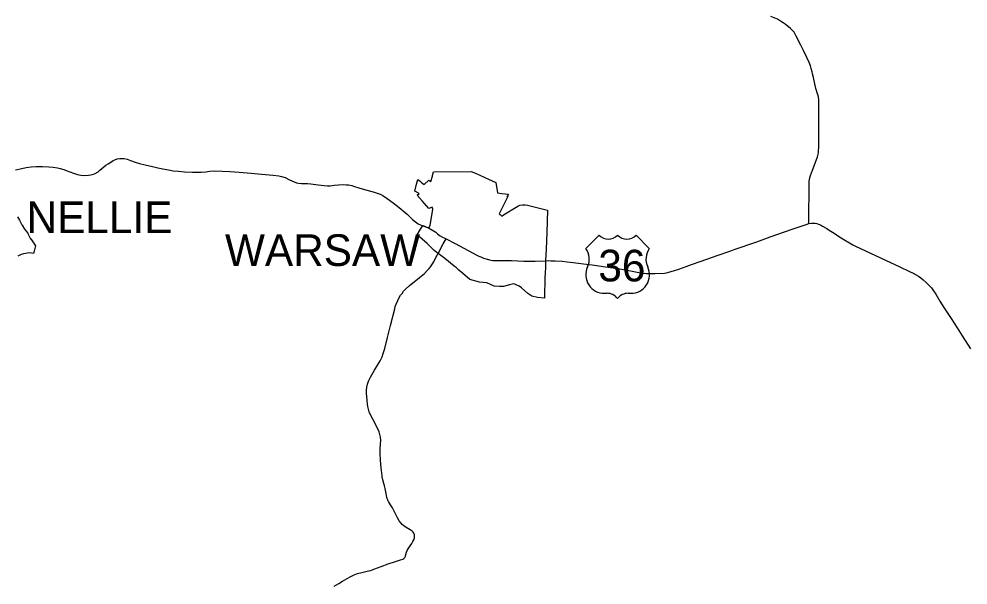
# Model space of a CAD drawing. Extents: x 2004415 to 2276415, y 751181 to 927181.
# Drawn here: x 2090901 to 2124487, y 838735 to 858783 of the extents above; entities that cross this region are included whole.
import ezdxf

# ---------------------------------------------------------------- set-up
doc = ezdxf.new("R2010")
doc.units = 0
for name, color, linetype in [('GM_X_Corporation', 7, 'Continuous'), ('GM_X_Corporation_Text', 7, 'Continuous'), ('GM_X_State_Route', 7, 'Continuous'), ('GM_X_US_Location', 7, 'Continuous'), ('GM_X_US_Route', 7, 'Continuous'), ('GM_X_US_Shield', 7, 'Continuous')]:
    doc.layers.add(name, color=color, linetype=linetype)

msp = doc.modelspace()

# ---------------------------------------------------------------- linework, layer by layer
at = {"layer": 'GM_X_Corporation'}
msp.add_lwpolyline([(2105113, 851335), (2105179, 851439), (2105179, 851439), (2105195, 851464), (2105195, 851464), (2105207, 851460), (2105227, 851454), (2105278, 851437), (2105334, 851414), (2105405, 851380), (2105455, 851471), (2105553, 852041), (2105519, 852116), (2105408, 852074), (2105248, 852242), (2105166, 852339), (2104993, 852542), (2105064, 852604), (2104911, 852690), (2104974, 852932), (2105015, 853092), (2105104, 853034), (2105152, 852992), (2105197, 852952), (2105199, 852950), (2105240, 852922), (2105404, 853072), (2105478, 853021), (2105531, 853219), (2105537, 853242), (2105572, 853370), (2106903, 853376), (2107057, 853326), (2107514, 853106), (2107775, 852990), (2107833, 852624), (2107987, 852607), (2108228, 852582), (2108167, 852483), (2108163, 852478), (2108188, 852485), (2108199, 852488), (2108206, 852491), (2107893, 851878), (2107901, 851874), (2107911, 851868), (2107920, 851861), (2107930, 851855), (2107939, 851848), (2107947, 851841), (2107956, 851834), (2107959, 851831), (2107964, 851826), (2107972, 851818), (2107980, 851810), (2107988, 851802), (2108054, 851844), (2108551, 852157), (2108632, 852189), (2108724, 852199), (2108819, 852196), (2108892, 852185), (2109602, 852017), (2109586, 851225), (2109558, 850625), (2109539, 850224), (2109530, 849966), (2109525, 849809), (2109515, 849607), (2109512, 849509), (2109501, 849036), (2109497, 848891), (2109257, 848922), (2109048, 848971), (2108983, 849013), (2108908, 849065), (2108681, 849258), (2108598, 849315), (2108540, 849349), (2108468, 849383), (2108407, 849398), (2108265, 849366), (2108054, 849310), (2107903, 849304), (2107715, 849322), (2107457, 849441), (2107193, 849460), (2106852, 849561), (2106597, 849775), (2106470, 849892), (2106369, 849976), (2106304, 850030), (2105967, 850303), (2105591, 850579), (2105346, 850835), (2104989, 851139)], close=True, dxfattribs=at)
msp.add_lwpolyline([(2090850, 851775), (2090914, 851654), (2091007, 851492), (2091012, 851484), (2091102, 851343), (2091210, 851198), (2091217, 851189), (2091313, 850998), (2091317, 850993), (2091489, 850744), (2091439, 850561), (2091431, 850531), (2091424, 850506), (2091416, 850477), (2091272, 850498), (2091200, 850490), (2091060, 850462), (2090973, 850436), (2090857, 850378)], dxfattribs=at)
at = {"layer": 'GM_X_State_Route'}
for p, q in [((2106014, 850995), (2106333, 850828)), ((2106333, 850828), (2106648, 850663)), ((2106648, 850663), (2106956, 850500)), ((2113103, 849770), (2113160, 849770))]:
    msp.add_line(p, q, dxfattribs=at)
for points in [[(2119159, 853904), (2119172, 853945), (2119183, 853994), (2119193, 854042), (2119200, 854129), (2119205, 854223), (2119208, 854361), (2119203, 854853), (2119202, 855057), (2119205, 855744), (2119203, 855928), (2119195, 856016), (2119185, 856068), (2119150, 856170), (2119121, 856253), (2119103, 856322), (2119018, 856708), (2118987, 856839), (2118971, 856905), (2118939, 857033), (2118917, 857119), (2118869, 857237), (2118784, 857422), (2118666, 857664), (2118641, 857712), (2118568, 857853), (2118406, 858175), (2118359, 858268), (2118331, 858313), (2118298, 858356), (2118208, 858440), (2118017, 858595), (2117946, 858649), (2117856, 858709), (2117739, 858771), (2117511, 858875)], [(2118849, 851535), (2118852, 851622), (2118850, 851891), (2118853, 851941), (2118859, 852212), (2118860, 852359), (2118862, 852648), (2118863, 852966), (2118867, 853043), (2118876, 853096), (2118888, 853152), (2118915, 853235), (2118982, 853425), (2119146, 853864), (2119159, 853904)], [(2116213, 850615), (2117014, 850894), (2117489, 851063), (2118268, 851336), (2118578, 851442), (2118759, 851506), (2118849, 851535)], [(2105858, 850711), (2105916, 850820), (2106014, 850995)], [(2103942, 847505), (2104051, 847924), (2104197, 848516), (2104220, 848605), (2104249, 848688), (2104303, 848818), (2104351, 848913), (2104406, 848998), (2104457, 849066), (2104510, 849137), (2104571, 849205), (2104705, 849329), (2105077, 849631), (2105251, 849774), (2105348, 849871), (2105416, 849946), (2105475, 850020), (2105513, 850077), (2105578, 850181), (2105632, 850285), (2105700, 850412), (2105793, 850588), (2105858, 850711)], [(2106956, 850500), (2107109, 850420), (2107174, 850383), (2107241, 850356)], [(2113160, 849770), (2113410, 849767), (2113747, 849782), (2113820, 849791), (2113904, 849810), (2114096, 849871), (2114250, 849925), (2114509, 850016), (2114707, 850086), (2115048, 850204), (2115610, 850401), (2116098, 850574), (2116213, 850615)], [(2107241, 850356), (2107340, 850317), (2107439, 850284)], [(2107439, 850284), (2107558, 850253), (2107676, 850234), (2107790, 850225), (2107947, 850225), (2108145, 850228), (2108329, 850223), (2108558, 850212), (2108771, 850203), (2108923, 850200), (2109174, 850206), (2109535, 850219), (2109624, 850223), (2109719, 850219)], [(2109719, 850219), (2109878, 850214), (2110125, 850203), (2110303, 850184), (2110518, 850156), (2110697, 850135), (2110884, 850109)], [(2110884, 850109), (2111184, 850070), (2111653, 850008), (2112009, 849955), (2112361, 849893), (2112599, 849847), (2112778, 849812), (2112950, 849782), (2113021, 849775), (2113103, 849770)], [(2104582, 839756), (2104595, 839814), (2104618, 839899), (2104644, 839959), (2104674, 840012), (2104747, 840125), (2104805, 840212), (2104845, 840277), (2104874, 840335), (2104895, 840404), (2104903, 840467), (2104899, 840512), (2104880, 840574), (2104856, 840610), (2104814, 840648), (2104742, 840693), (2104602, 840775), (2104519, 840833), (2104461, 840884), (2104410, 840939), (2104358, 841009), (2104301, 841116), (2104173, 841380), (2104121, 841472), (2104054, 841575), (2103981, 841688), (2103952, 841742), (2103924, 841830), (2103898, 841975), (2103863, 842155), (2103833, 842254), (2103811, 842329), (2103773, 842466), (2103757, 842565), (2103750, 842603), (2103723, 842887), (2103698, 843156), (2103680, 843390), (2103680, 843566), (2103693, 843728), (2103703, 843866), (2103699, 843967), (2103677, 844067), (2103646, 844155), (2103587, 844288), (2103424, 844604), (2103364, 844718), (2103294, 844875), (2103267, 844961), (2103245, 845059), (2103235, 845136), (2103223, 845278), (2103199, 845530), (2103197, 845635), (2103210, 845741), (2103237, 845851), (2103273, 845955), (2103340, 846094), (2103485, 846349), (2103680, 846672), (2103749, 846818), (2103791, 846934), (2103815, 847001), (2103847, 847109), (2103942, 847505)], [(2102051, 838694), (2102215, 838785), (2102349, 838868), (2102513, 838966), (2102648, 839042), (2102768, 839099), (2102882, 839140), (2103031, 839179), (2103269, 839235), (2103354, 839254), (2103462, 839292), (2103717, 839394), (2103963, 839486), (2104221, 839572), (2104407, 839625), (2104480, 839651), (2104525, 839678), (2104556, 839711), (2104582, 839756)]]:
    msp.add_lwpolyline(points, dxfattribs=at)
at = {"layer": 'GM_X_US_Route'}
for p, q in [((2105846, 851083), (2106014, 850995)), ((2106014, 850995), (2106333, 850828)), ((2106333, 850828), (2106648, 850663)), ((2106648, 850663), (2106956, 850500)), ((2113103, 849770), (2113160, 849770))]:
    msp.add_line(p, q, dxfattribs=at)
for points in [[(2090777, 853440), (2090999, 853488), (2091159, 853519), (2091336, 853543), (2091506, 853558), (2091737, 853559), (2091959, 853549), (2092113, 853539), (2092264, 853516), (2092357, 853492), (2092489, 853450), (2092568, 853422), (2092825, 853319), (2092969, 853273), (2093095, 853249), (2093224, 853241), (2093358, 853249), (2093449, 853263), (2093539, 853285), (2093598, 853309), (2093701, 853371), (2093764, 853426), (2093905, 853549), (2093980, 853606), (2094054, 853655), (2094151, 853717), (2094240, 853767), (2094299, 853797), (2094379, 853827), (2094468, 853842), (2094533, 853847), (2094618, 853838), (2094735, 853814), (2094850, 853773), (2095008, 853712), (2095161, 853668), (2095368, 853617), (2095622, 853555), (2095820, 853511), (2095995, 853474), (2096195, 853434), (2096363, 853408), (2096540, 853391), (2096758, 853373), (2097040, 853359), (2097191, 853352), (2097350, 853355), (2097510, 853373), (2097661, 853390), (2097813, 853399), (2098097, 853396), (2098365, 853385), (2098690, 853361), (2099119, 853324), (2099483, 853291), (2099893, 853250), (2100098, 853227), (2100196, 853207), (2100324, 853163), (2100475, 853091), (2100635, 853016), (2100724, 852985), (2100792, 852968), (2100898, 852956), (2101117, 852955), (2101232, 852943), (2101495, 852909), (2101705, 852885), (2101815, 852877), (2101918, 852878), (2102058, 852894), (2102205, 852909), (2102381, 852917), (2102476, 852914), (2102562, 852907), (2102678, 852882), (2102775, 852854), (2102931, 852806), (2103216, 852724), (2103435, 852662), (2103577, 852619), (2103681, 852575), (2103772, 852530), (2103926, 852430), (2104148, 852273), (2104356, 852110), (2104634, 851864), (2104826, 851684), (2104933, 851594), (2105026, 851531), (2105133, 851481)], [(2105133, 851481), (2105324, 851414), (2105385, 851388), (2105449, 851351), (2105590, 851269), (2105654, 851230), (2105694, 851198), (2105718, 851178), (2105787, 851120), (2105834, 851089), (2105846, 851083)], [(2116213, 850615), (2117014, 850894), (2117489, 851063), (2118268, 851336), (2118578, 851442), (2118759, 851506), (2118849, 851535)], [(2118849, 851535), (2118953, 851552), (2119016, 851554), (2119076, 851548), (2119132, 851535), (2119195, 851516), (2119263, 851488), (2119343, 851443), (2119488, 851358), (2119571, 851306), (2119746, 851196), (2119905, 851094), (2120097, 850971), (2120288, 850851), (2120406, 850782), (2120502, 850732), (2121561, 850239), (2122077, 850000), (2122414, 849845)], [(2106956, 850500), (2107109, 850420), (2107174, 850383), (2107241, 850356)], [(2113160, 849770), (2113410, 849767), (2113747, 849782), (2113820, 849791), (2113904, 849810), (2114096, 849871), (2114250, 849925), (2114509, 850016), (2114707, 850086), (2115048, 850204), (2115610, 850401), (2116098, 850574), (2116213, 850615)], [(2107241, 850356), (2107340, 850317), (2107439, 850284)], [(2107439, 850284), (2107558, 850253), (2107676, 850234), (2107790, 850225), (2107947, 850225), (2108145, 850228), (2108329, 850223), (2108558, 850212), (2108771, 850203), (2108923, 850200), (2109174, 850206), (2109535, 850219), (2109624, 850223), (2109719, 850219)], [(2109719, 850219), (2109878, 850214), (2110125, 850203), (2110303, 850184), (2110518, 850156), (2110697, 850135), (2110884, 850109)], [(2110884, 850109), (2111184, 850070), (2111653, 850008), (2112009, 849955), (2112361, 849893), (2112599, 849847), (2112778, 849812), (2112950, 849782), (2113021, 849775), (2113103, 849770)], [(2122414, 849845), (2122418, 849843), (2122546, 849782), (2122647, 849727), (2122732, 849674), (2122819, 849616), (2122903, 849549), (2123009, 849455), (2123116, 849343), (2123191, 849255), (2123266, 849150), (2123343, 849034), (2123492, 848792), (2123636, 848568), (2123893, 848169), (2124105, 847839), (2124283, 847556), (2124575, 847103)]]:
    msp.add_lwpolyline(points, dxfattribs=at)
at = {"layer": 'GM_X_US_Shield'}
for p, q in [((2111434, 851124), (2110967, 850657)), ((2113208, 850657), (2112741, 851124)), ((2111620, 849069), (2111714, 849069)), ((2112461, 849069), (2112554, 849069))]:
    msp.add_line(p, q, dxfattribs=at)
for centre, radius, start, end in [((2111760, 851457), 467, 225.573, 314.427), ((2112414, 851457), 467, 225.573, 314.427), ((2110431, 850282), 654, 334.5471, 35.0009), ((2113744, 850282), 654, 144.9991, 205.4529), ((2111613, 849723), 654, 154.8319, 270.6383), ((2112562, 849723), 654, 269.3617, 25.1681), ((2111714, 848602), 467, 36.8699, 90), ((2112461, 848602), 467, 90, 143.1301)]:
    msp.add_arc(centre, radius, start, end, dxfattribs=at)

# ---------------------------------------------------------------- texts
at = {"layer": 'GM_X_Corporation_Text'}
for s, p in [('NELLIE', (2091169, 851200)), ('WARSAW', (2098192, 850036))]:
    msp.add_text(s, height=1120, rotation=0, dxfattribs=at).set_placement(p)
at = {"layer": 'GM_X_US_Location'}
msp.add_text('36', height=1, rotation=0, dxfattribs=at).set_placement((2111477, 849819))
for s in ['0', '/']:
    msp.add_text(s, height=1, dxfattribs=at).set_placement((2111683, 850026))
at = {"layer": 'GM_X_US_Shield'}
msp.add_text('36', height=1120.7, dxfattribs=at).set_placement((2111404, 849489))

doc.saveas('drawing.dxf')
